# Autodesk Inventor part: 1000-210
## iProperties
Created: 2012-08
Part Number: 1000-210
Document SubType Name: Modeling
Designer: Administrator
Density: 1.06 g/cm^3
Material: ABS Plastic
Mass: 27.7242 g
Surface Area: 118.516 cm^2
Volume: 26.1549 cm^3
Author: Administrator
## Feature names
1. Base1
